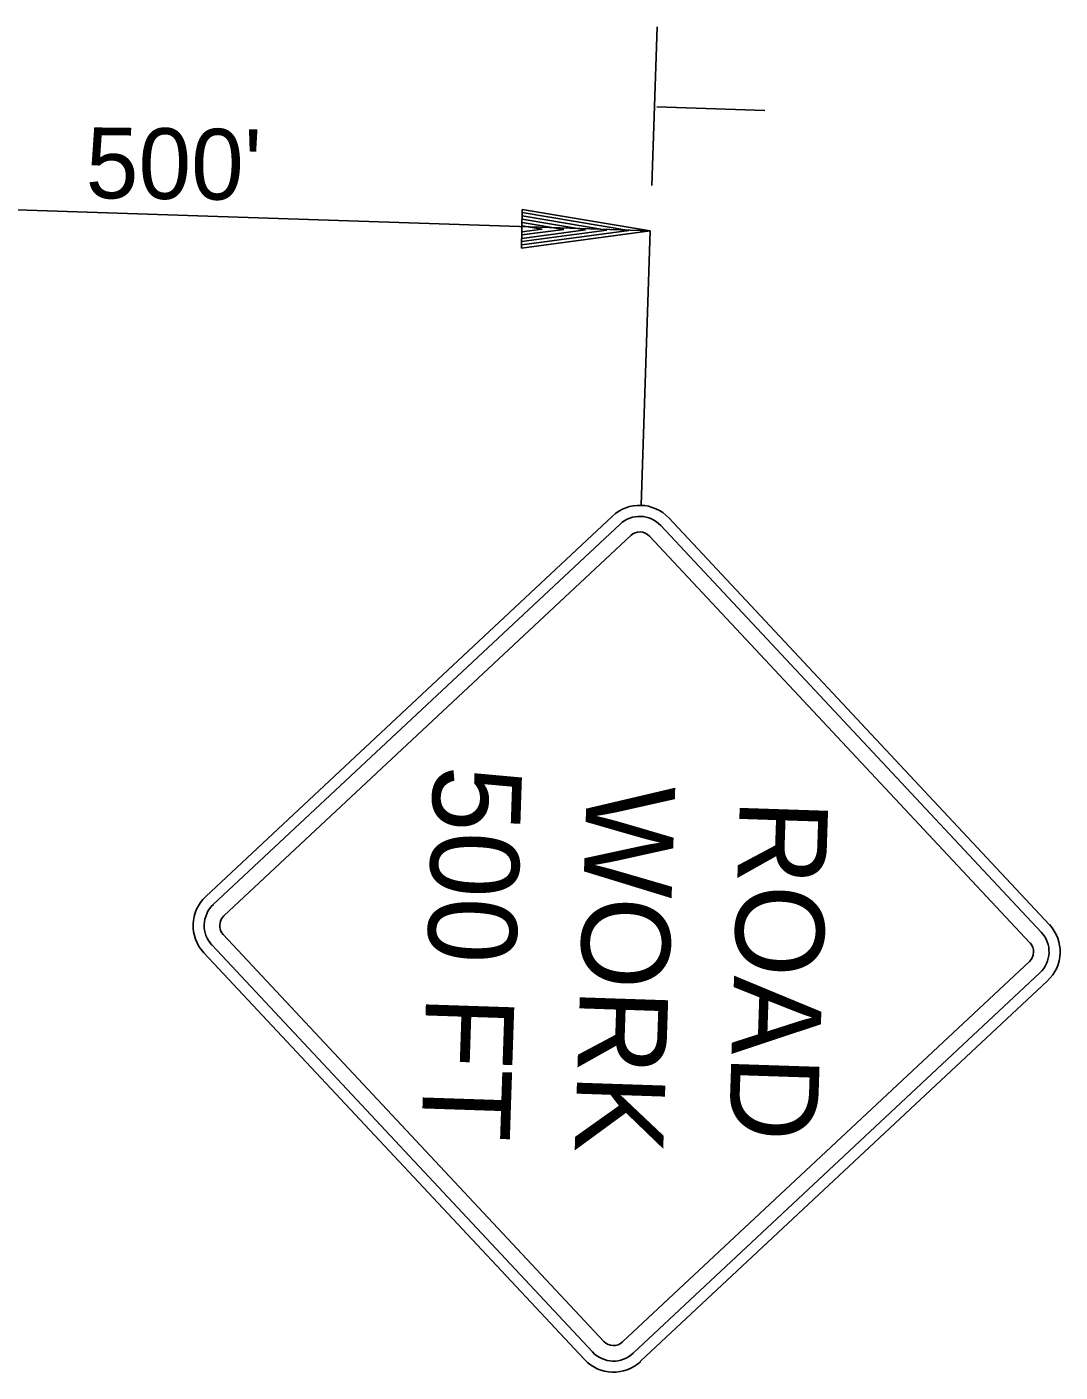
# Model space of a CAD drawing. Extents: x 977269 to 979191, y 1525946 to 1526973.
# Drawn here: x 977768.3 to 977856, y 1526499.7 to 1526613.8 of the extents above; entities that cross this region are included whole.
import ezdxf

# ---------------------------------------------------------------- set-up
doc = ezdxf.new("R2010")
doc.units = 0
doc.layers.add('STAMP', color=7, linetype='Continuous')
doc.layers.add('STAMP_PP', color=7, linetype='Continuous')

msp = doc.modelspace()

# ---------------------------------------------------------------- linework, layer by layer
at = {"layer": 'STAMP'}
for p, q in [((977821.32, 1526600.34), (977821.77, 1526613.8)), ((977821.74, 1526607.03), (977830.92, 1526606.72)), ((977821.19, 1526596.49), (977721.25, 1526599.82)), ((977810.34, 1526598.31), (977810.28, 1526595.04)), ((977810.33, 1526597.76), (977817.51, 1526596.55)), ((977810.33, 1526597.49), (977815.69, 1526596.58)), ((977810.34, 1526598.31), (977821.19, 1526596.49)), ((977810.34, 1526598.04), (977819.37, 1526596.52)), ((977810.28, 1526595.04), (977821.19, 1526596.49)), ((977810.29, 1526595.6), (977817.51, 1526596.55)), ((977810.29, 1526595.32), (977819.37, 1526596.52)), ((977810.3, 1526596.15), (977813.85, 1526596.62)), ((977810.3, 1526595.86), (977815.69, 1526596.58)), ((977810.31, 1526596.42), (977812.03, 1526596.65)), ((977810.32, 1526597.21), (977813.85, 1526596.62)), ((977810.32, 1526596.93), (977812.03, 1526596.65)), ((977821.19, 1526596.49), (977820.42, 1526573.21))]:
    msp.add_line(p, q, dxfattribs=at)
at = {"layer": 'STAMP_PP'}
for p, q in [((977783.49, 1526540.02), (977818, 1526572.3)), ((977784.13, 1526539.34), (977818.64, 1526571.61)), ((977822.08, 1526571.5), (977854.36, 1526536.99)), ((977822.77, 1526572.14), (977855.05, 1526537.63)), ((977785.03, 1526538.38), (977819.54, 1526570.66)), ((977821.13, 1526570.6), (977853.4, 1526536.1)), ((977816.3, 1526501.38), (977784.02, 1526535.89)), ((977817.26, 1526502.28), (977784.98, 1526536.79)), ((977815.61, 1526500.74), (977783.33, 1526535.25)), ((977853.35, 1526534.51), (977818.85, 1526502.23)), ((977854.25, 1526533.55), (977819.74, 1526501.27)), ((977854.89, 1526532.86), (977820.38, 1526500.59))]:
    msp.add_line(p, q, dxfattribs=at)
for centre, radius, start, end in [((977820.3, 1526569.83), 3.38, 43.0901, 133.0901), ((977820.3, 1526569.83), 2.44, 43.0901, 133.0901), ((977820.3, 1526569.83), 1.12, 43.0901, 133.0901), ((977785.8, 1526537.56), 3.38, 133.0901, 223.0901), ((977785.8, 1526537.56), 2.44, 133.0901, 223.0901), ((977785.8, 1526537.56), 1.13, 133.0901, 223.0901), ((977852.58, 1526535.33), 2.44, 313.0901, 43.0901), ((977852.58, 1526535.33), 3.38, 313.0901, 43.0901), ((977852.58, 1526535.33), 1.13, 313.0901, 43.0901), ((977818.08, 1526503.05), 1.12, 223.0901, 313.0901), ((977818.08, 1526503.05), 3.38, 223.0901, 313.0901), ((977818.08, 1526503.05), 2.44, 223.0901, 313.0901)]:
    msp.add_arc(centre, radius, start, end, dxfattribs=at)

# ---------------------------------------------------------------- texts
at = {"layer": 'STAMP'}
msp.add_text("500'", height=6, rotation=359.3204, dxfattribs=at).set_placement((977773.29, 1526599.28))
at = {"layer": 'STAMP_PP'}
for s, p in [('500 FT ', (977802.84, 1526551.2)), ('WORK', (977815.82, 1526549.55)), (' ROAD ', (977828.9, 1526551.15))]:
    msp.add_text(s, height=7.5, rotation=268.0901, dxfattribs=at).set_placement(p)

doc.saveas('drawing.dxf')
